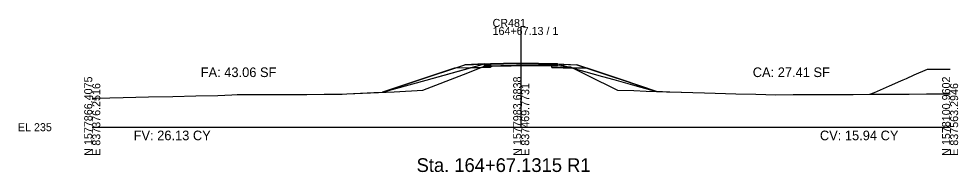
# Model space of a CAD drawing. Extents: x -26 to 303, y -16 to 6048.
# Drawn here: x -25.7 to 302.8, y 2484.3 to 2537.8 of the extents above; entities that cross this region are included whole.
import ezdxf

# ---------------------------------------------------------------- set-up
doc = ezdxf.new("R2010")
doc.units = 0
for name, color, linetype in [('ASPHALT_19MM1', 7, 'Continuous'), ('ASPHALT_9_5MM1', 7, 'Continuous'), ('Draft_XS_Grid', 7, 'Continuous'), ('Draft_XS_Text', 7, 'Continuous'), ('DTM_P_FINISHED_GRADE', 7, 'Continuous'), ('DTM_P_FINISHED_GRADE2', 7, 'Continuous'), ('DTM_TEMP_DROP', 7, 'Continuous'), ('DTM_X_FLOW_ARROWS', 7, 'Continuous'), ('DTM_X_GROUND', 7, 'Continuous'), ('TRANS_PAVED_SHOULDERS', 7, 'Continuous'), ('XS_CELL', 7, 'Continuous'), ('XS_M_SHAPES_EARTHWORK', 7, 'Continuous'), ('XS_P_ASPHALT', 7, 'Continuous'), ('XS_P_GROUND', 7, 'Continuous'), ('XS_P_NULL_POINT', 7, 'Continuous'), ('XS_P_SHOULDER', 7, 'Continuous'), ('XS_P_SUBGRADE_GRANULAR', 7, 'Continuous'), ('XS_P_SUBGRADE_LEVELING', 7, 'Continuous'), ('XS_P_SUBGRADE_MILLING', 7, 'Continuous'), ('XS_SHEET_EW_TX_AREA', 7, 'Continuous'), ('XS_SHEET_EW_TX_VOLUME', 7, 'Continuous')]:
    doc.layers.add(name, color=color, linetype=linetype)

msp = doc.modelspace()

# ---------------------------------------------------------------- linework, layer by layer
at = {"layer": 'ASPHALT_19MM1'}
for points in [[(139.22, 2521.79), (139.22, 2521.52), (137.22, 2521.48), (137.22, 2521.75), (139.22, 2521.79)], [(160.7, 2521.8), (160.7, 2521.53), (162.7, 2521.49), (162.7, 2521.76), (160.7, 2521.8)]]:
    msp.add_lwpolyline(points, dxfattribs=at)
at = {"layer": 'ASPHALT_9_5MM1'}
for points in [[(139.22, 2522.13), (139.22, 2522), (137.22, 2521.96), (137.22, 2522.09), (139.22, 2522.13)], [(160.7, 2522.13), (160.7, 2522), (162.7, 2521.96), (162.7, 2522.09), (160.7, 2522.13)]]:
    msp.add_lwpolyline(points, dxfattribs=at)
at = {"layer": 'DTM_P_FINISHED_GRADE'}
msp.add_lwpolyline([(292.06, 2520.3), (297.77, 2520.3), (298.12, 2520.3), (300, 2520.3)], dxfattribs=at)
at = {"layer": 'DTM_P_FINISHED_GRADE2'}
msp.add_lwpolyline([(101.48, 2512.21), (113.75, 2516.3), (130.28, 2521.81), (133.32, 2521.93), (137.22, 2522.09), (138.07, 2522.11), (139.22, 2522.13), (143.86, 2522.22), (150, 2522.34), (156.04, 2522.22), (160.7, 2522.13), (161.85, 2522.11), (162.7, 2522.09), (166.5, 2521.94), (169.41, 2521.82), (182.09, 2517.59), (185.33, 2516.51), (197.38, 2512.5)], dxfattribs=at)
at = {"layer": 'DTM_X_GROUND'}
for points in [[(0, 2510.12), (1.53, 2510.11), (10.83, 2510.33), (19.7, 2510.54), (28.16, 2510.75), (36.24, 2510.94), (43.96, 2511.12), (48.79, 2511.32), (50.68, 2511.36), (51.91, 2511.37), (60.37, 2511.37), (62.3, 2511.39), (75.08, 2511.46), (81.09, 2511.47), (84.11, 2511.48), (87.36, 2511.58), (89.01, 2511.63), (98.47, 2512.07), (101.48, 2512.21), (116.79, 2516.42), (137.22, 2522.09), (138.07, 2522.11), (139.22, 2522.13), (143.86, 2522.22), (150, 2522.34), (156.04, 2522.22), (160.7, 2522.13), (161.85, 2522.11), (162.7, 2522.09), (178.41, 2517.74), (182.43, 2516.63), (189.76, 2514.6), (197.38, 2512.5), (198.79, 2512.45), (199.43, 2512.43), (200.85, 2512.39), (202.02, 2512.35), (214.12, 2511.96), (217.81, 2511.87), (225.02, 2511.69), (232.11, 2511.5), (239.09, 2511.33), (245.15, 2511.38), (266.09, 2511.43), (272.9, 2511.48), (279.44, 2511.53), (285.72, 2511.58), (291.76, 2511.62), (297.58, 2511.67), (300, 2511.69)], [(0, 2510.12), (1.53, 2510.11), (10.83, 2510.33), (19.7, 2510.54), (28.16, 2510.75), (36.24, 2510.94), (43.96, 2511.12), (48.79, 2511.32), (50.68, 2511.36), (51.91, 2511.37), (60.37, 2511.37), (62.3, 2511.39), (75.08, 2511.46), (81.09, 2511.47), (84.11, 2511.48), (87.36, 2511.58), (89.01, 2511.63), (105.54, 2512.39), (115.57, 2512.9), (129.82, 2518.41), (137.22, 2521.27), (146.47, 2521.48), (149.97, 2521.56), (153.64, 2521.55), (162.7, 2521.52), (166.72, 2521.13), (167.27, 2521.08), (173.13, 2518.18), (183.66, 2512.97), (189.35, 2512.77), (193.73, 2512.61), (214.12, 2511.96), (217.81, 2511.87), (225.02, 2511.69), (232.11, 2511.5), (239.09, 2511.33), (245.15, 2511.38), (266.09, 2511.43), (272.9, 2511.48), (279.44, 2511.53), (285.72, 2511.58), (291.76, 2511.62), (297.58, 2511.67), (300, 2511.69)]]:
    msp.add_lwpolyline(points, dxfattribs=at)
at = {"layer": 'TRANS_PAVED_SHOULDERS'}
for points in [[(139.22, 2522), (139.22, 2521.79), (137.22, 2521.75), (137.22, 2521.96), (139.22, 2522)], [(160.7, 2522), (160.7, 2521.8), (162.7, 2521.76), (162.7, 2521.96), (160.7, 2522)]]:
    msp.add_lwpolyline(points, dxfattribs=at)
at = {"layer": 'XS_CELL'}
for p, q in [((150, 2500), (150, 2535)), ((0, 2500), (150, 2500)), ((150, 2500), (300, 2500))]:
    msp.add_line(p, q, dxfattribs=at)
at = {"layer": 'XS_M_SHAPES_EARTHWORK'}
for points in [[(101.48, 2512.21), (116.79, 2516.42), (132.28, 2520.72), (126.66, 2520.61), (113.75, 2516.3)], [(132.28, 2520.72), (137.22, 2522.09), (138.07, 2522.11), (139.22, 2522.13), (143.86, 2522.22), (150, 2522.34), (156.04, 2522.22), (160.7, 2522.13), (161.85, 2522.11), (162.7, 2522.09), (167.65, 2520.72), (164.7, 2520.78), (162.7, 2520.82), (160.7, 2520.86), (160.7, 2521.52), (160.34, 2521.53), (157.28, 2521.54), (151.59, 2521.55), (150, 2521.56), (149.99, 2521.56), (149.97, 2521.56), (148.33, 2521.53), (142.89, 2521.4), (139.9, 2521.33), (139.22, 2521.31), (139.22, 2520.86), (137.22, 2520.82), (135.22, 2520.78)], [(167.65, 2520.72), (178.41, 2517.74), (182.43, 2516.63), (189.76, 2514.6), (197.38, 2512.5), (185.33, 2516.51), (173.03, 2520.61)]]:
    msp.add_lwpolyline(points, close=True, dxfattribs=at)
at = {"layer": 'XS_P_ASPHALT'}
msp.add_lwpolyline([(139.22, 2522.07), (139.22, 2522), (143.86, 2522.1), (150, 2522.22), (156.04, 2522.1), (160.7, 2522), (160.7, 2522.08), (160.7, 2522.13), (156.04, 2522.22), (150, 2522.34), (143.86, 2522.22), (139.22, 2522.13), (139.22, 2522.07)], dxfattribs=at)
at = {"layer": 'XS_P_GROUND'}
for points in [[(101.48, 2512.21), (113.75, 2516.3), (130.28, 2521.81)], [(197.38, 2512.5), (185.33, 2516.51), (169.41, 2521.82)], [(271.95, 2511.47), (273.18, 2511.99), (273.56, 2512.15), (278.82, 2514.43), (282.82, 2516.16), (283.6, 2516.51), (284.77, 2517.03), (287.47, 2518.24), (292.06, 2520.3)]]:
    msp.add_lwpolyline(points, dxfattribs=at)
at = {"layer": 'XS_P_SHOULDER'}
for points in [[(137.22, 2522.09), (130.28, 2521.81)], [(162.7, 2522.09), (169.41, 2521.82)]]:
    msp.add_lwpolyline(points, dxfattribs=at)
at = {"layer": 'XS_P_SUBGRADE_GRANULAR'}
for points in [[(137.22, 2520.82), (135.22, 2520.78), (126.66, 2520.61)], [(139.22, 2520.86), (137.22, 2520.82)], [(139.22, 2520.86), (139.22, 2522.13)], [(160.7, 2520.86), (160.7, 2522.13)], [(160.7, 2520.86), (162.7, 2520.82)], [(162.7, 2520.82), (164.7, 2520.78), (173.03, 2520.61)]]:
    msp.add_lwpolyline(points, dxfattribs=at)
at = {"layer": 'XS_P_SUBGRADE_LEVELING'}
msp.add_lwpolyline([(157.28, 2522.07), (151.59, 2522.19), (150, 2522.22), (149.99, 2522.22), (149.97, 2522.22), (148.33, 2522.19), (142.89, 2522.08), (139.9, 2522.02), (139.22, 2522), (139.22, 2521.7), (139.22, 2521.31), (139.9, 2521.33), (142.89, 2521.4), (148.33, 2521.53), (149.97, 2521.56), (149.99, 2521.56), (150, 2521.56), (151.59, 2521.55), (157.28, 2521.54), (160.34, 2521.53), (160.7, 2521.52), (160.7, 2521.79), (160.7, 2522), (160.34, 2522.01), (157.28, 2522.07)], dxfattribs=at)
at = {"layer": 'XS_P_SUBGRADE_MILLING'}
for points in [[(160.7, 2521.52), (160.7, 2521.52), (160.34, 2521.53), (157.28, 2521.54), (151.59, 2521.55), (150, 2521.56), (149.99, 2521.56), (149.97, 2521.56), (148.33, 2521.53), (142.89, 2521.4), (139.9, 2521.33), (139.22, 2521.31), (139.22, 2521.31)], [(139.22, 2521.31), (139.9, 2521.33), (142.89, 2521.4), (148.33, 2521.53), (149.97, 2521.56), (149.99, 2521.56), (150, 2521.56), (151.59, 2521.55), (157.28, 2521.54), (160.34, 2521.53), (160.7, 2521.52)]]:
    msp.add_lwpolyline(points, dxfattribs=at)

# ---------------------------------------------------------------- texts
at = {"layer": 'Draft_XS_Grid'}
msp.add_text('-', height=0.0001, dxfattribs=at).set_placement((0, 2500))
at = {"layer": 'Draft_XS_Text'}
msp.add_text('Sta. 164+67.1315 R1', height=4.8, dxfattribs=at).set_placement((113.42, 2484.35))
at = {"layer": 'DTM_TEMP_DROP'}
for p in [(291.98, 2520.18), (101.4, 2512.09), (197.3, 2512.38)]:
    msp.add_text('X', height=0.24, dxfattribs=at).set_placement(p)
at = {"layer": 'DTM_X_FLOW_ARROWS'}
msp.add_text('X', height=0.24, dxfattribs=at).set_placement((271.87, 2511.35))
at = {"layer": 'XS_CELL'}
for s, p in [('CR481', (140, 2535)), ('164+67.13 / 1', (140, 2532.2)), ('EL 235', (-26, 2498.6))]:
    msp.add_text(s, height=2.8, dxfattribs=at).set_placement(p)
for s, p in [('N 1577866.4075', (0, 2490)), ('N 1577983.6838', (150, 2490)), ('N 1578100.9602', (300, 2490)), ('E 837376.2516', (2.8, 2490)), ('E 837469.7731', (152.8, 2490)), ('E 837563.2946', (302.8, 2490))]:
    msp.add_text(s, height=2.8, rotation=90, dxfattribs=at).set_placement(p)
at = {"layer": 'XS_P_GROUND'}
for p in [(130.2, 2521.69), (169.33, 2521.7)]:
    msp.add_text('X', height=0.24, dxfattribs=at).set_placement(p)
at = {"layer": 'XS_P_NULL_POINT'}
for p in [(137.14, 2521.97), (139.14, 2522.01), (149.92, 2522.22), (160.62, 2522.01), (162.62, 2521.97)]:
    msp.add_text('X', height=0.24, dxfattribs=at).set_placement(p)
at = {"layer": 'XS_P_SUBGRADE_GRANULAR'}
for p in [(101.4, 2512.09), (197.3, 2512.38)]:
    msp.add_text('X', height=0.24, dxfattribs=at).set_placement(p)
at = {"layer": 'XS_SHEET_EW_TX_AREA'}
for s, p in [('FA: 43.06 SF', (37.93, 2517.5)), ('CA: 27.41 SF', (230.99, 2517.5))]:
    msp.add_text(s, height=3.36, dxfattribs=at).set_placement(p)
at = {"layer": 'XS_SHEET_EW_TX_VOLUME'}
for s, p in [('FV: 26.13 CY', (14.47, 2495.44)), ('CV: 15.94 CY', (254.47, 2495.44))]:
    msp.add_text(s, height=3.36, dxfattribs=at).set_placement(p)

doc.saveas('drawing.dxf')
